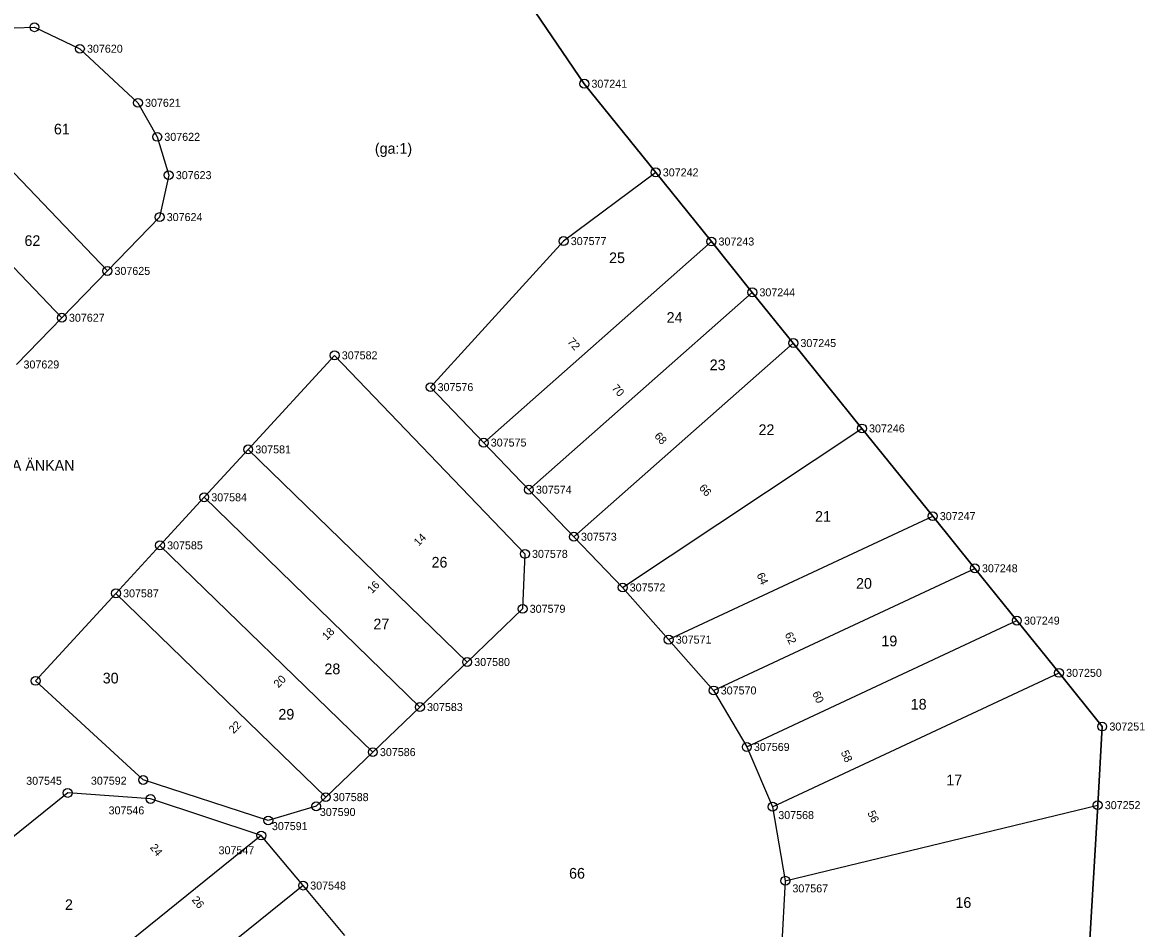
# Model space of a CAD drawing. Extents: x 141995 to 152570, y 6580184 to 6586000.
# Drawn here: x 142279.5 to 142405.7, y 6585497.2 to 6585599.2 of the extents above; entities that cross this region are included whole.
import ezdxf

# ---------------------------------------------------------------- set-up
doc = ezdxf.new("R2010")
doc.units = 0
for name, color, linetype in [('Level 10', 7, 'Continuous'), ('Level 5', 7, 'Continuous'), ('Level 50', 7, 'Continuous'), ('Level 51', 7, 'Continuous'), ('Level 53', 7, 'Continuous'), ('Level 54', 7, 'Continuous'), ('Level 6', 7, 'Continuous'), ('Level 7', 7, 'Continuous')]:
    doc.layers.add(name, color=color, linetype=linetype)

msp = doc.modelspace()

# ---------------------------------------------------------------- linework, layer by layer
at = {"layer": 'Level 10'}
for centre in [(142280.81, 6585598.61), (142285.92, 6585596.18), (142342.66, 6585592.25), (142292.45, 6585590.1), (142294.62, 6585586.27), (142350.69, 6585582.27), (142295.91, 6585581.96), (142294.89, 6585577.24), (142340.33, 6585574.54), (142356.96, 6585574.49), (142289.01, 6585571.18), (142361.56, 6585568.77), (142283.89, 6585565.91), (142366.17, 6585563.06), (142314.57, 6585561.68), (142325.36, 6585558.1), (142373.89, 6585553.45), (142331.34, 6585551.85), (142304.85, 6585551.09), (142299.9, 6585545.7), (142336.42, 6585546.56), (142381.85, 6585543.58), (142341.49, 6585541.26), (142294.93, 6585540.29), (142335.98, 6585539.33), (142386.59, 6585537.7), (142346.97, 6585535.55), (142289.98, 6585534.89), (142335.72, 6585533.15), (142391.32, 6585531.82), (142352.15, 6585529.68), (142329.48, 6585527.16), (142396.06, 6585525.94), (142280.94, 6585525.04), (142357.21, 6585523.96), (142324.17, 6585522.09), (142400.92, 6585519.9), (142318.87, 6585517.02), (142360.94, 6585517.6), (142293.04, 6585513.89), (142284.55, 6585512.43), (142293.87, 6585511.75), (142313.58, 6585511.95), (142312.5, 6585510.92), (142363.84, 6585510.87), (142400.41, 6585511.05), (142307.11, 6585509.32), (142306.32, 6585507.63), (142365.27, 6585502.54), (142311.03, 6585502)]:
    msp.add_circle(centre, 0.5, dxfattribs=at)
at = {"layer": 'Level 5'}
for points in [[(142323.23, 6585620.83), (142342.66, 6585592.25)], [(142342.66, 6585592.25), (142350.69, 6585582.27)], [(142350.69, 6585582.27), (142356.96, 6585574.49)], [(142356.96, 6585574.49), (142361.56, 6585568.77)], [(142361.56, 6585568.77), (142366.17, 6585563.06)], [(142366.17, 6585563.06), (142373.89, 6585553.45)], [(142373.89, 6585553.45), (142381.85, 6585543.58)], [(142381.85, 6585543.58), (142386.59, 6585537.7)], [(142386.59, 6585537.7), (142391.32, 6585531.82)], [(142391.32, 6585531.82), (142396.06, 6585525.94)], [(142396.06, 6585525.94), (142400.92, 6585519.9)], [(142400.92, 6585519.9), (142400.41, 6585511.05)], [(142400.41, 6585511.05), (142399.47, 6585494.64)]]:
    msp.add_lwpolyline(points, dxfattribs=at)
at = {"layer": 'Level 6'}
msp.add_lwpolyline([(142351.05, 6585397.5), (142389.52, 6585397.37), (142396.55, 6585404.35), (142396.68, 6585442.89), (142396.69, 6585446.39), (142397.47, 6585459.87), (142398.21, 6585472.66), (142398.63, 6585479.99), (142399.04, 6585487.32), (142399.47, 6585494.64), (142400.41, 6585511.05), (142400.92, 6585519.9), (142396.06, 6585525.94), (142391.32, 6585531.82), (142386.59, 6585537.7), (142381.85, 6585543.58), (142373.89, 6585553.45), (142366.17, 6585563.06), (142361.56, 6585568.77), (142356.96, 6585574.49), (142350.69, 6585582.27), (142342.66, 6585592.25), (142323.23, 6585620.83)], dxfattribs=at)
at = {"layer": 'Level 7'}
for points in [[(142276.21, 6585598.48), (142280.81, 6585598.61)], [(142280.81, 6585598.61), (142285.92, 6585596.18)], [(142285.92, 6585596.18), (142292.45, 6585590.1)], [(142289.01, 6585571.18), (142267.24, 6585593.96)], [(142292.45, 6585590.1), (142294.62, 6585586.27)], [(142283.89, 6585565.91), (142262.25, 6585588.56)], [(142294.62, 6585586.27), (142295.91, 6585581.96)], [(142295.91, 6585581.96), (142294.89, 6585577.24)], [(142350.69, 6585582.27), (142340.33, 6585574.54)], [(142294.89, 6585577.24), (142289.01, 6585571.18)], [(142340.33, 6585574.54), (142325.36, 6585558.1)], [(142331.34, 6585551.85), (142356.96, 6585574.49)], [(142289.01, 6585571.18), (142283.89, 6585565.91)], [(142336.42, 6585546.56), (142361.56, 6585568.77)], [(142283.89, 6585565.91), (142278.78, 6585560.65)], [(142341.49, 6585541.26), (142366.17, 6585563.06)], [(142304.85, 6585551.09), (142314.57, 6585561.68)], [(142314.57, 6585561.68), (142335.98, 6585539.33)], [(142325.36, 6585558.1), (142331.34, 6585551.85)], [(142346.97, 6585535.55), (142373.89, 6585553.45)], [(142299.9, 6585545.7), (142304.85, 6585551.09)], [(142304.85, 6585551.09), (142329.48, 6585527.16)], [(142331.34, 6585551.85), (142336.42, 6585546.56)], [(142336.42, 6585546.56), (142341.49, 6585541.26)], [(142294.93, 6585540.29), (142299.9, 6585545.7)], [(142299.9, 6585545.7), (142324.17, 6585522.09)], [(142352.15, 6585529.68), (142381.85, 6585543.58)], [(142341.49, 6585541.26), (142346.97, 6585535.55)], [(142289.98, 6585534.89), (142294.93, 6585540.29)], [(142294.93, 6585540.29), (142318.87, 6585517.02)], [(142335.98, 6585539.33), (142335.72, 6585533.15)], [(142357.21, 6585523.96), (142386.59, 6585537.7)], [(142280.94, 6585525.04), (142289.98, 6585534.89)], [(142289.98, 6585534.89), (142313.58, 6585511.95)], [(142346.97, 6585535.55), (142352.15, 6585529.68)], [(142335.72, 6585533.15), (142329.48, 6585527.16)], [(142360.94, 6585517.6), (142391.32, 6585531.82)], [(142352.15, 6585529.68), (142357.21, 6585523.96)], [(142329.48, 6585527.16), (142324.17, 6585522.09)], [(142363.84, 6585510.87), (142396.06, 6585525.94)], [(142293.04, 6585513.89), (142280.94, 6585525.04)], [(142357.21, 6585523.96), (142360.94, 6585517.6)], [(142324.17, 6585522.09), (142318.87, 6585517.02)], [(142318.87, 6585517.02), (142313.58, 6585511.95)], [(142360.94, 6585517.6), (142363.84, 6585510.87)], [(142307.11, 6585509.32), (142293.04, 6585513.89)], [(142284.55, 6585512.43), (142265.8, 6585497.34)], [(142293.87, 6585511.75), (142284.55, 6585512.43)], [(142313.58, 6585511.95), (142312.5, 6585510.92)], [(142306.32, 6585507.63), (142293.87, 6585511.75)], [(142312.5, 6585510.92), (142307.11, 6585509.32)], [(142363.84, 6585510.87), (142365.27, 6585502.54)], [(142365.27, 6585502.54), (142400.41, 6585511.05)], [(142306.32, 6585507.63), (142277.92, 6585484.71)], [(142311.03, 6585502), (142306.32, 6585507.63)], [(142311.03, 6585502), (142282.99, 6585479.38)], [(142315.73, 6585496.38), (142311.03, 6585502)], [(142365.27, 6585502.54), (142364.84, 6585494.86)]]:
    msp.add_lwpolyline(points, dxfattribs=at)

# ---------------------------------------------------------------- texts
at = {"layer": 'Level 50'}
msp.add_text('GLADA ÄNKAN', height=1.2, rotation=0.0527, dxfattribs=at).set_placement((142273.9, 6585548.68))
at = {"layer": 'Level 51'}
for s, p in [('61', (142283, 6585586.55)), ('62', (142279.69, 6585573.99)), ('25', (142345.45, 6585572.06)), ('24', (142351.92, 6585565.34)), ('23', (142356.77, 6585560.01)), ('22', (142362.26, 6585552.71)), ('21', (142368.62, 6585542.95)), ('26', (142325.48, 6585537.79)), ('20', (142373.23, 6585535.41)), ('27', (142318.94, 6585530.84)), ('19', (142376.08, 6585528.93)), ('30', (142288.49, 6585524.75)), ('28', (142313.43, 6585525.79)), ('18', (142379.38, 6585521.81)), ('29', (142308.25, 6585520.68)), ('17', (142383.38, 6585513.28)), ('66', (142340.95, 6585502.78)), ('16', (142384.41, 6585499.49)), ('2', (142284.24, 6585499.25))]:
    msp.add_text(s, height=1.2, rotation=0.0527, dxfattribs=at).set_placement(p)
msp.add_text('(ga:1)', height=1.2, dxfattribs=at).set_placement((142319.1, 6585584.37))
at = {"layer": 'Level 53'}
for s, p in [('307620', (142286.72, 6585595.74)), ('307241', (142343.46, 6585591.8)), ('307621', (142293.25, 6585589.65)), ('307622', (142295.42, 6585585.82)), ('307242', (142351.49, 6585581.82)), ('307623', (142296.71, 6585581.51)), ('307624', (142295.69, 6585576.79)), ('307577', (142341.14, 6585574.09)), ('307243', (142357.76, 6585574.04)), ('307625', (142289.81, 6585570.73)), ('307244', (142362.36, 6585568.32)), ('307627', (142284.69, 6585565.46)), ('307245', (142366.97, 6585562.61)), ('307629', (142279.58, 6585560.2)), ('307582', (142315.38, 6585561.23)), ('307576', (142326.16, 6585557.65)), ('307246', (142374.69, 6585553)), ('307575', (142332.14, 6585551.41)), ('307581', (142305.65, 6585550.64)), ('307584', (142300.7, 6585545.25)), ('307574', (142337.22, 6585546.11)), ('307247', (142382.65, 6585543.13)), ('307573', (142342.29, 6585540.81)), ('307585', (142295.73, 6585539.84)), ('307578', (142336.78, 6585538.88)), ('307248', (142387.39, 6585537.26)), ('307572', (142347.77, 6585535.1)), ('307587', (142290.78, 6585534.44)), ('307579', (142336.52, 6585532.7)), ('307249', (142392.12, 6585531.37)), ('307571', (142352.95, 6585529.23)), ('307580', (142330.28, 6585526.71)), ('307250', (142396.86, 6585525.49)), ('307570', (142358.01, 6585523.51)), ('307583', (142324.97, 6585521.64)), ('307251', (142401.73, 6585519.45)), ('307586', (142319.67, 6585516.57)), ('307569', (142361.74, 6585517.15)), ('307545', (142279.88, 6585513.34)), ('307592', (142287.16, 6585513.35)), ('307588', (142314.38, 6585511.5)), ('307546', (142289.15, 6585510.01)), ('307590', (142312.91, 6585509.83)), ('307252', (142401.21, 6585510.6)), ('307568', (142364.48, 6585509.48)), ('307591', (142307.52, 6585508.24)), ('307547', (142301.52, 6585505.52)), ('307548', (142311.83, 6585501.55)), ('307567', (142366.07, 6585501.23))]:
    msp.add_text(s, height=0.9, rotation=0.0527, dxfattribs=at).set_placement(p)
at = {"layer": 'Level 54'}
for s, rotation, p in [('72', 311.3883, (142340.71, 6585563.17)), ('70', 311.3883, (142345.69, 6585557.95)), ('68', 311.3883, (142350.48, 6585552.56)), ('66', 311.3883, (142355.5, 6585546.72)), ('14', 45.5445, (142324.02, 6585540.14)), ('64', 294.8817, (142362.02, 6585536.97)), ('16', 45.5445, (142318.78, 6585534.81)), ('18', 45.5445, (142313.7, 6585529.56)), ('62', 294.8817, (142365.19, 6585530.28)), ('20', 45.5445, (142308.25, 6585524.19)), ('60', 294.8817, (142368.28, 6585523.64)), ('22', 45.5445, (142303.21, 6585519.04)), ('58', 294.8817, (142371.49, 6585516.98)), ('56', 294.8817, (142374.48, 6585510.19)), ('24', 308.8752, (142293.75, 6585506.26)), ('26', 308.8752, (142298.45, 6585500.37))]:
    msp.add_text(s, height=0.9, rotation=rotation, dxfattribs=at).set_placement(p)

doc.saveas('drawing.dxf')
